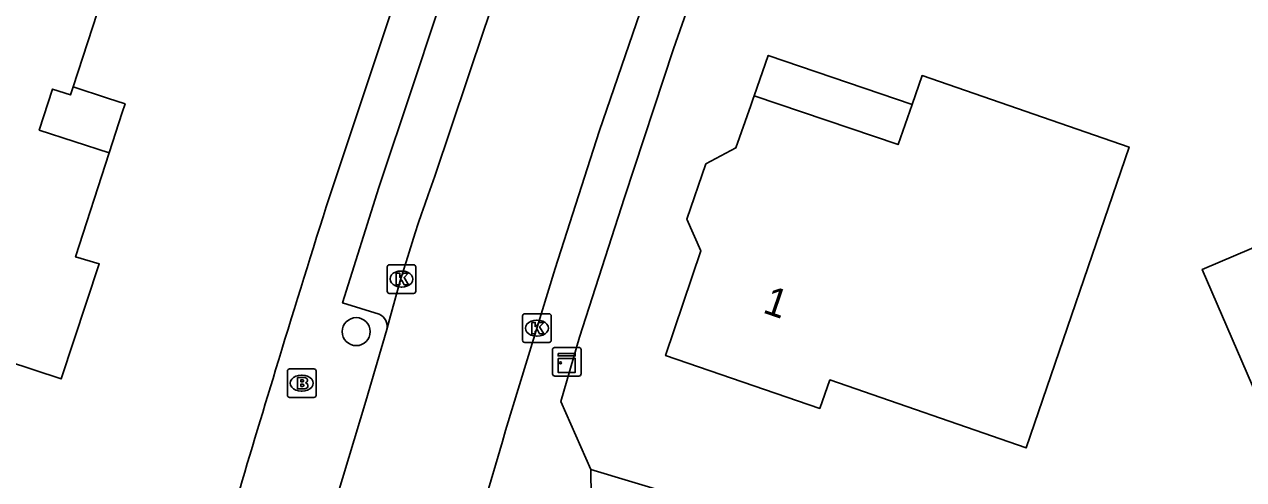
# Model space of a CAD drawing. Extents: x 157767 to 159171, y 387842 to 389425.
# Drawn here: x 158052.76 to 158095.37, y 388785.14 to 388801.04 of the extents above; entities that cross this region are included whole.
import ezdxf

# ---------------------------------------------------------------- set-up
doc = ezdxf.new("R2010")
doc.units = 0
for name, color, linetype in [('IMGEO_Boom', 7, 'Continuous'), ('IMGEO_Brandkraan', 7, 'Continuous'), ('IMGEO_Kast', 7, 'Continuous'), ('IMGEO_Kolk', 7, 'Continuous'), ('IMGEO_Pand', 7, 'Continuous'), ('IMGEO_Pand_nummerreeks', 7, 'Continuous'), ('IMGEO_Pand_overbouw', 7, 'Continuous'), ('IMGEO_Rijbaan_lokaal_open', 7, 'Continuous'), ('IMGEO_Voetpad_open', 7, 'Continuous')]:
    doc.layers.add(name, color=color, linetype=linetype)

msp = doc.modelspace()

# ---------------------------------------------------------------- linework, layer by layer
at = {"layer": 'IMGEO_Boom'}
msp.add_circle((158064.354, 388790.305), 0.489, dxfattribs=at)
at = {"layer": 'IMGEO_Brandkraan'}
for p, q in [((158061.95, 388788.08), (158061.95, 388788.932)), ((158062.025, 388789.006), (158062.877, 388789.006)), ((158062.951, 388788.932), (158062.951, 388788.08)), ((158062.438, 388788.786), (158062.463, 388788.786)), ((158062.461, 388788.226), (158062.436, 388788.226)), ((158062.877, 388788.006), (158062.025, 388788.006))]:
    msp.add_line(p, q, dxfattribs=at)
for points in [[(158061.95, 388788.08), (158061.95, 388788.932)], [(158062.025, 388789.006), (158062.877, 388789.006)], [(158062.951, 388788.932), (158062.951, 388788.08)], [(158062.298, 388788.706), (158062.298, 388788.306), (158062.511, 388788.306)], [(158062.529, 388788.706), (158062.298, 388788.706)], [(158062.477, 388788.625), (158062.423, 388788.625), (158062.423, 388788.549)], [(158062.423, 388788.549), (158062.476, 388788.549)], [(158062.485, 388788.473), (158062.423, 388788.473), (158062.423, 388788.392)], [(158062.423, 388788.392), (158062.485, 388788.392)], [(158062.877, 388788.006), (158062.025, 388788.006)]]:
    msp.add_lwpolyline(points, dxfattribs=at)
for centre, radius, start, end in [((158062.027, 388788.93), 0.0765, 91.552, 178.448), ((158062.027, 388788.93), 0.0765, 91.552, 178.448), ((158062.875, 388788.93), 0.0765, 1.552, 88.448), ((158062.875, 388788.93), 0.0765, 1.552, 88.448), ((158062.478, 388788.587), 0.0379, 267.8285, 90.9355), ((158062.486, 388788.432), 0.0404, 269.8759, 90.5077), ((158062.533, 388788.561), 0.145, 59.4692, 91.5367), ((158062.558, 388788.608), 0.0922, 285.5137, 58.1501), ((158062.563, 388788.416), 0.105, 301.3115, 78.989), ((158062.027, 388788.082), 0.0765, 181.552, 268.448), ((158062.027, 388788.082), 0.0765, 181.552, 268.448), ((158062.517, 388788.557), 0.251, 268.6676, 293.5347), ((158062.875, 388788.082), 0.0765, 271.552, 358.448), ((158062.875, 388788.082), 0.0765, 271.552, 358.448)]:
    msp.add_arc(centre, radius, start, end, dxfattribs=at)
for centre, major_axis, ratio, start_param, end_param in [((158062.437, 388788.506), (-0.387, 0.002), 0.722429, 4.712389, 7.853982), ((158062.462, 388788.506), (-0.39, 0.002), 0.717154, 1.570796, 4.712389)]:
    msp.add_ellipse(centre, major_axis=major_axis, ratio=ratio, start_param=start_param, end_param=end_param, dxfattribs=at)
at = {"layer": 'IMGEO_Kast'}
for p, q in [((158071.29, 388789.753), (158072.131, 388789.753)), ((158072.131, 388789.753), (158071.29, 388789.753)), ((158071.215, 388788.828), (158071.215, 388789.669)), ((158071.215, 388789.669), (158071.215, 388788.828)), ((158072.215, 388789.678), (158072.215, 388788.837)), ((158072.215, 388788.837), (158072.215, 388789.678)), ((158072.14, 388788.753), (158071.299, 388788.753)), ((158071.299, 388788.753), (158072.14, 388788.753))]:
    msp.add_line(p, q, dxfattribs=at)
for points in [[(158071.41, 388789.543), (158072.01, 388789.543), (158072.01, 388789.458), (158071.41, 388789.458), (158071.41, 388789.543)], [(158071.41, 388789.368), (158072.01, 388789.368), (158072.01, 388788.879), (158071.41, 388788.879), (158071.41, 388789.368)]]:
    msp.add_lwpolyline(points, dxfattribs=at)
msp.add_circle((158071.494, 388789.217), 0.0377, dxfattribs=at)
for centre, start, end in [((158071.293, 388789.675), 92.4484, 184.2845), ((158071.293, 388789.675), 92.4484, 184.2845), ((158072.137, 388789.675), 2.4484, 94.2845), ((158072.137, 388789.675), 2.4484, 94.2845), ((158071.293, 388788.831), 182.4484, 274.2845), ((158071.293, 388788.831), 182.4484, 274.2845), ((158072.137, 388788.831), 272.4484, 4.2845), ((158072.137, 388788.831), 272.4484, 4.2845)]:
    msp.add_arc(centre, 0.0779, start, end, dxfattribs=at)
at = {"layer": 'IMGEO_Kolk'}
for p, q in [((158065.436, 388791.717), (158065.436, 388792.569)), ((158065.511, 388792.643), (158066.363, 388792.643)), ((158065.924, 388792.423), (158065.949, 388792.423)), ((158066.437, 388792.569), (158066.437, 388791.717)), ((158065.947, 388791.863), (158065.922, 388791.863)), ((158066.363, 388791.643), (158065.511, 388791.643)), ((158070.171, 388790.002), (158070.171, 388790.854)), ((158070.246, 388790.928), (158071.098, 388790.928)), ((158070.659, 388790.708), (158070.684, 388790.708)), ((158071.172, 388790.854), (158071.172, 388790.002)), ((158070.682, 388790.148), (158070.657, 388790.148)), ((158071.098, 388789.928), (158070.246, 388789.928))]:
    msp.add_line(p, q, dxfattribs=at)
for points in [[(158065.436, 388791.717), (158065.436, 388792.569)], [(158065.511, 388792.643), (158066.363, 388792.643)], [(158065.757, 388792.343), (158065.88, 388792.343), (158065.88, 388792.192), (158066.01, 388792.343), (158066.174, 388792.343), (158066.028, 388792.192), (158066.181, 388791.943), (158066.029, 388791.943), (158065.944, 388792.107), (158065.88, 388792.04), (158065.88, 388791.943), (158065.757, 388791.943), (158065.757, 388792.343)], [(158066.437, 388792.569), (158066.437, 388791.717)], [(158066.363, 388791.643), (158065.511, 388791.643)], [(158070.171, 388790.002), (158070.171, 388790.854)], [(158070.246, 388790.928), (158071.098, 388790.928)], [(158070.492, 388790.628), (158070.615, 388790.628), (158070.615, 388790.477), (158070.745, 388790.628), (158070.909, 388790.628), (158070.763, 388790.477), (158070.916, 388790.228), (158070.764, 388790.228), (158070.679, 388790.392), (158070.615, 388790.325), (158070.615, 388790.228), (158070.492, 388790.228), (158070.492, 388790.628)], [(158071.172, 388790.854), (158071.172, 388790.002)], [(158071.098, 388789.928), (158070.246, 388789.928)]]:
    msp.add_lwpolyline(points, dxfattribs=at)
for centre, start, end in [((158065.513, 388792.567), 91.552, 178.448), ((158065.513, 388792.567), 91.552, 178.448), ((158066.361, 388792.567), 1.552, 88.448), ((158066.361, 388792.567), 1.552, 88.448), ((158065.513, 388791.719), 181.552, 268.448), ((158065.513, 388791.719), 181.552, 268.448), ((158066.361, 388791.719), 271.552, 358.448), ((158066.361, 388791.719), 271.552, 358.448), ((158070.248, 388790.852), 91.552, 178.448), ((158070.248, 388790.852), 91.552, 178.448), ((158071.096, 388790.852), 1.552, 88.448), ((158071.096, 388790.852), 1.552, 88.448), ((158070.248, 388790.004), 181.552, 268.448), ((158070.248, 388790.004), 181.552, 268.448), ((158071.096, 388790.004), 271.552, 358.448), ((158071.096, 388790.004), 271.552, 358.448)]:
    msp.add_arc(centre, 0.0765, start, end, dxfattribs=at)
for centre, major_axis, ratio, start_param, end_param in [((158065.923, 388792.143), (-0.387, 0.002), 0.722429, 4.712389, 7.853982), ((158065.948, 388792.143), (-0.39, 0.002), 0.717154, 1.570796, 4.712389), ((158070.658, 388790.428), (-0.387, 0.002), 0.722429, 4.712389, 7.853982), ((158070.683, 388790.428), (-0.39, 0.002), 0.717154, 1.570796, 4.712389)]:
    msp.add_ellipse(centre, major_axis=major_axis, ratio=ratio, start_param=start_param, end_param=end_param, dxfattribs=at)
at = {"layer": 'IMGEO_Pand'}
for points in [[(158049.291, 388790.222), (158044.58, 388791.779), (158046.037, 388796.278), (158040.579, 388798.053), (158042.142, 388802.858), (158045.342, 388801.817), (158046.45, 388805.248), (158051.023, 388803.77), (158055.776, 388802.22), (158055.677, 388801.913), (158055.476, 388801.979), (158054.462, 388798.851), (158054.372, 388798.574), (158053.741, 388798.778), (158053.275, 388797.342), (158055.723, 388796.548), (158054.544, 388792.914), (158055.372, 388792.675), (158054.038, 388788.653), (158049.291, 388790.222)], [(158112.009, 388792.192), (158111.402, 388791.962), (158111.102, 388792.762), (158104.047, 388789.771), (158105.08, 388787.353), (158105.683, 388785.942), (158103.459, 388784.961), (158103.62, 388784.578), (158098.336, 388782.268), (158096.353, 388786.858), (158093.926, 388792.476), (158101.828, 388795.84), (158101.291, 388797.104), (158108.593, 388800.213), (158110.05, 388796.793), (158112.009, 388792.192)], [(158083.295, 388796.841), (158083.781, 388798.24), (158084.132, 388799.248), (158091.37, 388796.749), (158087.776, 388786.242), (158080.914, 388788.62), (158080.559, 388787.624), (158075.168, 388789.467), (158076.405, 388793.132), (158075.907, 388794.233), (158076.577, 388796.166), (158077.623, 388796.72), (158078.147, 388798.209), (158078.22, 388798.418), (158078.265, 388798.546), (158083.295, 388796.841)]]:
    msp.add_lwpolyline(points, dxfattribs=at)
at = {"layer": 'IMGEO_Pand_overbouw'}
for points in [[(158083.781, 388798.24), (158078.758, 388799.954), (158078.265, 388798.546), (158083.295, 388796.841)], [(158054.462, 388798.851), (158054.372, 388798.574), (158053.741, 388798.778), (158053.275, 388797.342), (158055.723, 388796.548), (158056.18, 388797.956), (158056.279, 388798.26), (158055.661, 388798.461)]]:
    msp.add_lwpolyline(points, close=True, dxfattribs=at)
at = {"layer": 'IMGEO_Rijbaan_lokaal_open'}
for points in [[(158067.107, 388795.738), (158068.841, 388800.899), (158071.45, 388808.439), (158073.183, 388813.191), (158075.245, 388818.661), (158077.318, 388823.9), (158078.001, 388825.622), (158078.937, 388827.861)], [(158076.962, 388809.047), (158074.934, 388803.373), (158072.849, 388797.296), (158071.307, 388792.507), (158069.577, 388786.857), (158069.463, 388786.47), (158068.181, 388782.133), (158067.349, 388779.447), (158066.905, 388777.879), (158066.359, 388775.954)], [(158065.43, 388790.385), (158064.692, 388787.874), (158063.276, 388783.209), (158062.008, 388778.815), (158061.414, 388776.868)]]:
    msp.add_lwpolyline(points, dxfattribs=at)
msp.add_arc((158118.512, 388776.695), 54.819, 159.6724, 165.5379, dxfattribs=at)
at = {"layer": 'IMGEO_Voetpad_open'}
for points in [[(158063.307, 388794.667), (158065.859, 388802.325), (158067.683, 388807.671), (158069.525, 388812.795), (158071.843, 388819.001), (158074.122, 388824.808), (158076.221, 388830.037), (158078.528, 388835.608), (158080.771, 388840.788)], [(158072.557, 388785.494), (158071.511, 388787.861), (158072.155, 388790.113), (158073.73, 388794.988), (158075.44, 388800.18), (158077.124, 388804.963), (158079.161, 388810.597), (158080.476, 388813.945), (158081.065, 388815.496), (158082.965, 388820.428), (158084.94, 388825.383), (158086.884, 388830.077), (158089.41, 388836.039), (158089.846, 388837.076)], [(158183.864, 388823.28), (158161.367, 388806.591), (158159.023, 388804.985), (158096.685, 388778.239), (158072.557, 388785.494)], [(158069.148, 388803.055), (158067.857, 388803.496), (158066.35, 388798.93), (158065.143, 388795.337), (158063.878, 388791.31), (158065.162, 388790.912)], [(158072.59, 388782.615), (158072.557, 388785.494)]]:
    msp.add_lwpolyline(points, dxfattribs=at)
for centre, radius, start, end in [((158673.74, 388601.996), 640.118, 162.48271, 163.016658), ((158064.967, 388790.481), 0.473, 348.264, 65.6462), ((158645.448, 388610.697), 610.518, 163.022123, 163.955654)]:
    msp.add_arc(centre, radius, start, end, dxfattribs=at)

# ---------------------------------------------------------------- texts
at = {"layer": 'IMGEO_Pand_nummerreeks'}
msp.add_text('1', height=1, rotation=341.1262, dxfattribs=at).set_placement((158078.526, 388790.983))

doc.saveas('drawing.dxf')
